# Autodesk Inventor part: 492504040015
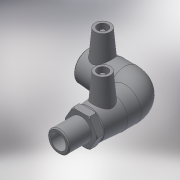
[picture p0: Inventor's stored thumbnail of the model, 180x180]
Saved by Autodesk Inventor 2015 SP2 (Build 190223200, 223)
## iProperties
Created: 2017-06
Part Number: 492504040015
Material: Generic
Description: PLASSON 90° ELBOW MALE TRANSITION 40-1.1/2"
Document SubType Name: Modeling
Designer: KIM
Mass: 207.505 g
Surface Area: 512.082 cm^2
Volume: 207.505 cm^3
Density: 1 g/cm^3
Appearance: Default
Author: KIM
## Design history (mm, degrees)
derived "492504.ipt"
feature "Solid1::492504.ipt"
tag "TaggingFeature1"
body "Solid1"
other parameters: "d2" = 56, "d4" = 30.66667, "d5" = 50.4, "d8" = 168 deg, "d10" = 17.6, "d11" = 5.86667, "d29" = 47, "d30" = 15, "d31" = 50.6, "d34" = 5 deg, "d41" = 4, "d42" = 14, "d43" = 0, "d48" = 64, "d50" = 34, "d51" = 17.6, "d52" = 44, "d54" = 90 deg, "d58" = 44, "d59" = 0, "d61" = 90 deg, "d86" = 3, "d87" = 0, "d93" = 0.1, "d94" = 9, "d95" = 47.803, "d96" = 33.4621, "d97" = 29, "d98" = 36, "d99" = 56, "d100" = 32.4, "d102" = 2, "d106" = 0, "L_" = 128, "L_1" = 44, "D_" = 29, "A_" = 47, "d_2" = 12, "L_2" = 36, "D_1" = 56, "R_" = 47.803
